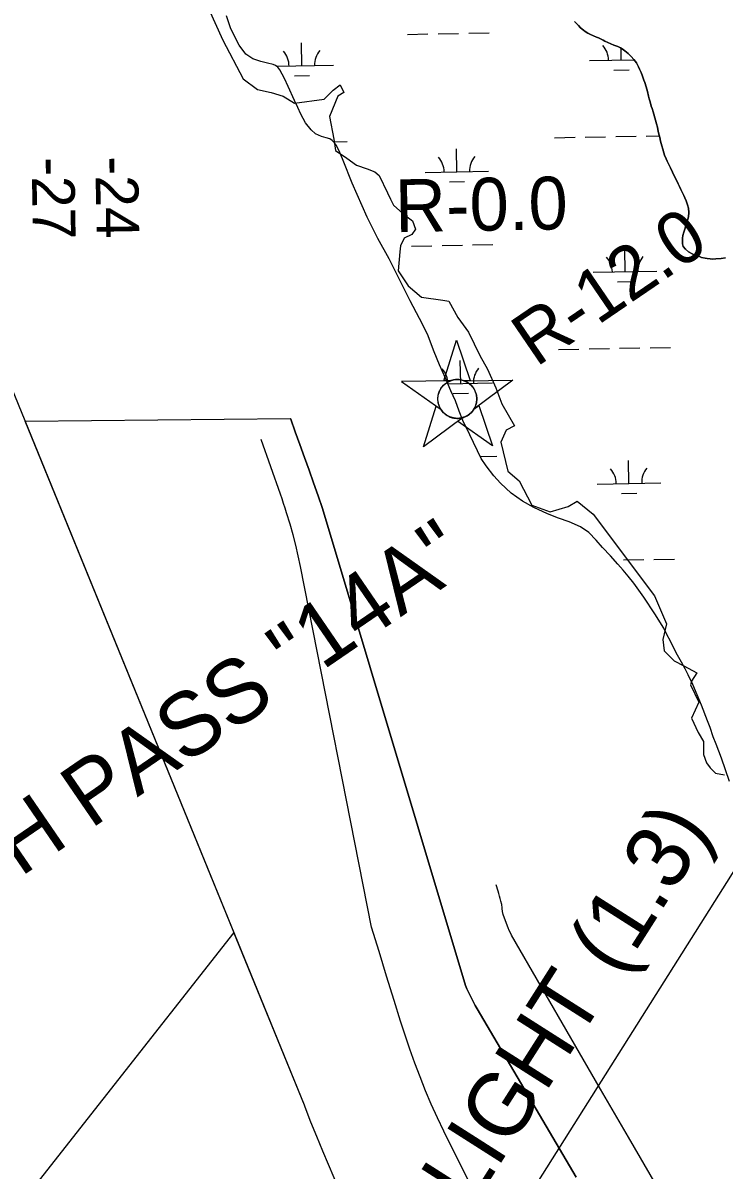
# Model space of a CAD drawing. Extents: x 3925854 to 3964121, y 224593 to 250589.
# Drawn here: x 3946690 to 3947792, y 237787 to 239589 of the extents above; entities that cross this region are included whole.
import ezdxf

# ---------------------------------------------------------------- set-up
doc = ezdxf.new("R2010")
doc.units = 0
for name, color, linetype in [('V-CHAN-NAID', 7, 'Continuous'), ('V-RIVR-EDGE', 7, 'Continuous'), ('V-RIVR-RANG', 7, 'Continuous'), ('V-RIVR-RANG-IDEN', 7, 'Continuous'), ('V-TOPO-DPTH', 7, 'Continuous'), ('V-TOPO-MINR', 7, 'Continuous'), ('V-TOPO-SHOR', 7, 'Continuous'), ('V-UTIL-LINE', 7, 'Continuous'), ('V-WETL-SWMP', 7, 'Continuous')]:
    doc.layers.add(name, color=color, linetype=linetype)

msp = doc.modelspace()

# ---------------------------------------------------------------- linework, layer by layer
at = {"layer": 'V-CHAN-NAID'}
for points in [[(3947361.111, 239026.765), (3947351.525, 239026.646), (3947371.41, 239090.529), (3947392.873, 239027.158), (3947383.286, 239027.04), (3947381.698, 239027.587), (3947379.592, 239028.166), (3947377.543, 239028.577), (3947375.502, 239028.845), (3947374.333, 239028.936), (3947372.797, 239028.988), (3947371.076, 239028.952), (3947369.707, 239028.855), (3947367.805, 239028.617), (3947366.444, 239028.372), (3947364.668, 239027.953), (3947363.146, 239027.503), (3947362.121, 239027.152)], [(3947361.111, 239026.765), (3947284.624, 239025.817), (3947347.062, 238981.625), (3947345.912, 238983.512), (3947345.07, 238985.124), (3947344.207, 238987.076), (3947343.471, 238989.116), (3947343.081, 238990.431), (3947342.688, 238992.05), (3947342.416, 238993.49), (3947342.197, 238995.084), (3947342.054, 238996.818), (3947342.011, 238998.398), (3947342.078, 239000.474), (3947342.229, 239002.095), (3947342.578, 239004.305), (3947343.022, 239006.237), (3947343.588, 239008.136), (3947344.21, 239009.827), (3947344.906, 239011.429), (3947345.69, 239012.98), (3947346.717, 239014.737), (3947347.719, 239016.227), (3947348.694, 239017.515), (3947349.674, 239018.68), (3947350.956, 239020.043), (3947351.988, 239021.028), (3947353.678, 239022.458), (3947354.873, 239023.351), (3947356.538, 239024.454), (3947358.251, 239025.433), (3947359.683, 239026.145)], [(3947383.286, 239027.04), (3947459.774, 239027.986), (3947398.45, 238982.261), (3947399.332, 238983.768), (3947400.274, 238985.634), (3947400.958, 238987.232), (3947401.659, 238989.201), (3947402.169, 238990.996), (3947402.535, 238992.643), (3947402.857, 238994.66), (3947403.012, 238996.236), (3947403.093, 238998.444), (3947403.023, 239000.505), (3947402.792, 239002.721), (3947402.491, 239004.473), (3947401.957, 239006.695), (3947401.275, 239008.822), (3947400.487, 239010.789), (3947399.811, 239012.22), (3947398.767, 239014.116), (3947397.671, 239015.817), (3947396.425, 239017.495), (3947395.134, 239019.009), (3947393.835, 239020.35), (3947392.174, 239021.85), (3947390.404, 239023.227), (3947388.698, 239024.371), (3947386.789, 239025.466), (3947385.303, 239026.199)], [(3947380.674, 238969.007), (3947319.35, 238923.282), (3947339.235, 238987.164), (3947347.062, 238981.625), (3947347.715, 238980.674), (3947349.134, 238978.842), (3947350.375, 238977.45), (3947351.87, 238975.976), (3947353.283, 238974.752), (3947354.759, 238973.625), (3947356.181, 238972.665), (3947357.879, 238971.662), (3947359.61, 238970.785), (3947361.417, 238970.009), (3947362.873, 238969.481), (3947364.511, 238968.984), (3947366.748, 238968.463), (3947368.285, 238968.206), (3947370.315, 238967.989), (3947371.854, 238967.915), (3947373.715, 238967.929), (3947375.402, 238968.04), (3947377.108, 238968.249), (3947379.004, 238968.597)], [(3947398.45, 238982.261), (3947406.136, 238987.993), (3947427.598, 238924.622), (3947372.987, 238963.276), (3947380.674, 238969.007), (3947382.33, 238969.515), (3947383.931, 238970.106), (3947386.071, 238971.062), (3947387.788, 238971.98), (3947389.632, 238973.13), (3947391.347, 238974.376), (3947392.875, 238975.651), (3947394.139, 238976.843), (3947395.495, 238978.29), (3947396.671, 238979.715), (3947397.762, 238981.209)]]:
    msp.add_lwpolyline(points, close=True, dxfattribs=at)
msp.add_circle((3947372.551, 238998.447), 30.541, dxfattribs=at)
at = {"layer": 'V-RIVR-EDGE'}
msp.add_lwpolyline([(3946981.586, 239611.735), (3947004.143, 239561.872), (3947036.198, 239501.325), (3947058.755, 239484.704), (3947080.125, 239479.955), (3947099.12, 239474.019), (3947116.928, 239463.334), (3947163.23, 239469.27), (3947177.476, 239483.516), (3947188.161, 239491.827), (3947194.097, 239479.955), (3947184.6, 239474.019), (3947171.54, 239441.964), (3947178.664, 239406.348), (3947181.038, 239388.539), (3947198.846, 239376.667), (3947214.28, 239365.982), (3947230.901, 239360.046), (3947242.773, 239355.298), (3947249.896, 239349.361), (3947262.956, 239322.056), (3947267.704, 239312.558), (3947272.453, 239303.06), (3947286.7, 239290.001), (3947302.134, 239278.129), (3947306.882, 239265.069), (3947300.946, 239256.759), (3947289.074, 239250.823), (3947283.138, 239238.951), (3947281.951, 239229.453), (3947279.577, 239199.773), (3947295.01, 239176.028), (3947316.38, 239158.22), (3947349.622, 239153.471), (3947359.12, 239152.284), (3947373.366, 239126.165), (3947389.987, 239103.608), (3947407.796, 239066.805), (3947419.668, 239045.435), (3947432.727, 239015.755), (3947442.225, 238990.823), (3947462.407, 238956.394), (3947449.348, 238949.271), (3947441.037, 238930.275), (3947451.722, 238885.161), (3947469.531, 238869.728), (3947489.713, 238831.737), (3947518.206, 238821.052), (3947546.699, 238829.362), (3947560.946, 238837.673), (3947585.877, 238817.49), (3947682.042, 238689.271), (3947701.037, 238645.344), (3947695.101, 238620.413), (3947697.475, 238602.605), (3947712.909, 238587.171), (3947728.343, 238578.861), (3947748.526, 238568.176), (3947740.215, 238555.116), (3947739.028, 238549.18), (3947752.087, 238521.874), (3947740.215, 238496.943), (3947750.9, 238474.386), (3947759.21, 238460.139), (3947759.21, 238448.267), (3947759.21, 238439.957), (3947763.959, 238426.897), (3947769.895, 238418.587), (3947778.206, 238410.276), (3947792.452, 238407.902)], dxfattribs=at)
at = {"layer": 'V-TOPO-DPTH'}
for points in [[(3946693.353, 238963.382), (3947110.256, 238967.95), (3947110.719, 238966.678), (3947117.981, 238946.654), (3947125.226, 238926.622), (3947132.458, 238906.587), (3947139.633, 238886.532), (3947146.747, 238866.454), (3947153.766, 238846.344), (3947160.724, 238826.212), (3947385.365, 238077.061), (3947387.577, 238071.644), (3947389.976, 238066.307), (3947392.498, 238061.022), (3947395.166, 238055.807), (3947397.905, 238050.63), (3947400.75, 238045.51), (3947403.666, 238040.429), (3947559.317, 237775.587)], [(3947132.294, 237888.663), (3946693.353, 238963.382)], [(3947021.379, 238160.231), (3946609.327, 237636.162)], [(3947132.294, 237888.663), (3947021.379, 238160.231)], [(3947188.051, 237753.814), (3947161.353, 237816.515), (3947151.809, 237839.392), (3947142.489, 237862.357), (3947133.505, 237885.456), (3947132.294, 237888.663)], [(3947188.051, 237753.814), (3947161.353, 237816.515), (3947151.809, 237839.392), (3947142.489, 237862.357), (3947133.505, 237885.456), (3947132.294, 237888.663)]]:
    msp.add_lwpolyline(points, dxfattribs=at)
at = {"layer": 'V-TOPO-MINR'}
for points in [[(3947132.294, 237888.663), (3946552.118, 239309.184), (3946236.204, 240123.225), (3945960.773, 240945.447)], [(3947559.317, 237775.587), (3947403.666, 238040.429), (3947400.75, 238045.51), (3947397.905, 238050.63), (3947395.166, 238055.807), (3947392.498, 238061.022), (3947389.976, 238066.307), (3947387.577, 238071.644), (3947385.365, 238077.061), (3947160.724, 238826.212), (3947153.766, 238846.344), (3947146.747, 238866.454), (3947139.633, 238886.532), (3947132.458, 238906.587), (3947125.226, 238926.622), (3947117.981, 238946.654), (3947110.719, 238966.678), (3947110.256, 238967.95)], [(3947390.846, 237768.494), (3947370.764, 237808.925), (3947351.227, 237848.155), (3947341.174, 237869.083), (3947331.526, 237890.189), (3947322.485, 237911.562), (3947313.848, 237933.113), (3947305.731, 237954.873), (3947297.903, 237976.732), (3947290.508, 237998.742), (3947283.401, 238020.853), (3947273.33, 238053.283), (3947261.434, 238091.693), (3947249.579, 238130.115), (3947237.785, 238168.556), (3947126.175, 238735.081), (3947122.67, 238751.847), (3947118.814, 238768.527), (3947114.43, 238785.075), (3947109.695, 238801.536), (3947104.241, 238819.422), (3947101.921, 238826.859), (3947099.537, 238834.275), (3947097.058, 238841.66), (3947094.515, 238849.024), (3947064.333, 238934.64)], [(3947684.829, 237763.478), (3947641.152, 237838.801), (3947597.516, 237914.148), (3947457.669, 238155.86), (3947456.281, 238158.356), (3947454.368, 238162.188), (3947453.243, 238164.81), (3947452.728, 238166.141), (3947444.518, 238188.391), (3947443.407, 238193.038), (3947443.105, 238197.833), (3947443.028, 238199.916), (3947442.624, 238202.862), (3947442.292, 238204.317), (3947440.926, 238209.4), (3947439.84, 238213.384), (3947438.737, 238217.364), (3947437.608, 238221.337), (3947436.461, 238225.305), (3947433.685, 238234.787)], [(3947188.051, 237753.814), (3947161.353, 237816.515), (3947151.809, 237839.392), (3947142.489, 237862.357), (3947133.505, 237885.456), (3947132.294, 237888.663)]]:
    msp.add_lwpolyline(points, dxfattribs=at)
at = {"layer": 'V-TOPO-SHOR'}
for points in [[(3947690.467, 239409.087), (3947689.498, 239413.032), (3947688.728, 239416.671), (3947687.571, 239421.826), (3947686.903, 239425.463), (3947685.445, 239430.825), (3947683.79, 239436.491), (3947682.721, 239440.336), (3947680.964, 239446.002), (3947679.889, 239449.441), (3947678.435, 239454.903), (3947677.259, 239458.446), (3947675.797, 239463.304), (3947674.724, 239466.745), (3947674.05, 239469.878), (3947672.987, 239474.326), (3947671.144, 239481.507), (3947669.002, 239488.691), (3947666.854, 239495.572), (3947665.481, 239499.521), (3947663.526, 239505.39), (3947661.068, 239511.467), (3947658.897, 239516.331), (3947657.121, 239519.98), (3947653.857, 239526.268), (3947649.779, 239531.756), (3947645.511, 239536.583), (3947641.118, 239540.925), (3947635.617, 239545.359), (3947631.593, 239548.327), (3947628.687, 239550.172), (3947624.452, 239552.232), (3947618.422, 239554.454), (3947604.146, 239560.774), (3947601.438, 239562.317), (3947597.625, 239564.172), (3947594.01, 239565.823), (3947590.895, 239566.863), (3947586.277, 239568.929), (3947581.659, 239570.994), (3947577.342, 239572.956), (3947573.235, 239575.721), (3947570.632, 239577.664), (3947566.237, 239581.746), (3947562.739, 239584.908), (3947559.147, 239588.779), (3947556.556, 239591.63)], [(3947794.01, 239220.001), (3947786.735, 239218.967), (3947778.66, 239218.347), (3947773.315, 239218.3), (3947769.786, 239218.64), (3947764.75, 239219.094), (3947761.727, 239219.631), (3947756.296, 239220.896), (3947752.878, 239222.041), (3947749.058, 239223.393), (3947746.144, 239224.331), (3947741.624, 239226.195), (3947735.505, 239229.486), (3947730.909, 239233.768), (3947727.523, 239237.94), (3947726.358, 239242.39), (3947726.106, 239247.234), (3947726.145, 239250.965), (3947726.792, 239255.094), (3947728.259, 239260.222), (3947729.721, 239265.049), (3947731.495, 239270.78), (3947733.571, 239276.508), (3947734.829, 239281.034), (3947735.474, 239284.759), (3947736.15, 239291.612), (3947735.412, 239298.376), (3947734.255, 239303.433), (3947731.9, 239309.81), (3947729.93, 239314.369), (3947728.353, 239317.816), (3947725.586, 239323.493), (3947723.612, 239327.648), (3947721.742, 239332.005), (3947719.569, 239336.568), (3947716.206, 239343.058), (3947712.852, 239350.052), (3947710.679, 239354.612), (3947707.42, 239361.303), (3947705.045, 239365.665), (3947702.184, 239371.949), (3947700.41, 239375.901), (3947698.149, 239381.673), (3947697.078, 239385.216), (3947695.321, 239390.88), (3947693.66, 239396.144), (3947692.691, 239399.988), (3947691.62, 239403.629), (3947690.467, 239409.087)]]:
    msp.add_lwpolyline(points, dxfattribs=at)
at = {"layer": 'V-UTIL-LINE'}
msp.add_line((3947949.336, 238483.295), (3945978.591, 235358.555), dxfattribs=at)
at = {"layer": 'V-WETL-SWMP'}
for p, q in [((3947294.366, 239571.233), (3947326.361, 239571.815)), ((3947342.358, 239572.106), (3947374.353, 239572.687)), ((3947390.35, 239572.978), (3947422.345, 239573.56)), ((3947128.174, 239521.773), (3947127.519, 239557.767)), ((3947629.999, 239530.898), (3947629.66, 239549.554)), ((3947580.007, 239529.989), (3947650.145, 239531.264)), ((3947088.695, 239521.056), (3947178.166, 239522.682)), ((3947618.281, 239515.251), (3947642.277, 239515.688)), ((3947116.456, 239506.127), (3947140.452, 239506.563)), ((3947177.837, 239402.586), (3947199.501, 239402.979)), ((3947525.355, 239408.905), (3947557.35, 239409.486)), ((3947573.347, 239409.777), (3947605.342, 239410.359)), ((3947621.34, 239410.65), (3947653.334, 239411.232)), ((3947669.332, 239411.522), (3947689.777, 239411.894)), ((3947371.711, 239355.36), (3947371.057, 239391.354)), ((3947321.72, 239354.451), (3947421.703, 239356.269)), ((3947359.994, 239339.714), (3947383.99, 239340.15)), ((3947300.414, 239238.613), (3947332.409, 239239.195)), ((3947348.406, 239239.486), (3947380.401, 239240.067)), ((3947396.398, 239240.358), (3947428.393, 239240.94)), ((3947636.047, 239198.278), (3947635.392, 239234.272)), ((3947586.055, 239197.369), (3947686.039, 239199.187)), ((3947624.329, 239182.631), (3947648.325, 239183.068)), ((3947531.403, 239076.284), (3947563.398, 239076.866)), ((3947579.396, 239077.157), (3947611.39, 239077.739)), ((3947627.388, 239078.03), (3947659.382, 239078.612)), ((3947675.38, 239078.902), (3947707.374, 239079.484)), ((3947377.76, 239022.74), (3947377.105, 239058.734)), ((3947357.425, 239022.371), (3947427.751, 239023.649)), ((3947366.042, 239007.094), (3947390.038, 239007.53)), ((3947408.579, 238907.85), (3947434.441, 238908.32)), ((3947642.095, 238865.658), (3947641.44, 238901.652)), ((3947592.103, 238864.749), (3947692.087, 238866.567)), ((3947630.377, 238850.011), (3947654.374, 238850.448)), ((3947633.436, 238745.41), (3947665.43, 238745.992)), ((3947681.428, 238746.282), (3947713.422, 238746.864))]:
    msp.add_line(p, q, dxfattribs=at)
for points in [[(3947548.419, 238805.415), (3947531.332, 238811.14), (3947513.952, 238817.877), (3947492.572, 238827.882), (3947474.621, 238837.953), (3947457.298, 238850.136), (3947440.317, 238866.148), (3947429.947, 238877.653), (3947417.702, 238893.212), (3947409.956, 238904.952), (3947392.208, 238942.295), (3947381.344, 238964.598), (3947375.548, 238979.485), (3947369.36, 238995.587), (3947362.159, 239011.194), (3947353.791, 239030.95), (3947344.728, 239051.822), (3947336.169, 239072.689), (3947325.463, 239100.437), (3947313.309, 239124.77), (3947298.266, 239152.563), (3947265.462, 239218.465), (3947247.54, 239250.726), (3947231.059, 239283.799), (3947207.107, 239337.607), (3947193.253, 239373.053), (3947186.655, 239388.453), (3947182.305, 239396.97), (3947179.419, 239400.732), (3947176.031, 239404.701), (3947172.224, 239407.161), (3947166.188, 239408.737), (3947158.947, 239410.729), (3947149.61, 239414.961), (3947142.613, 239421.085), (3947133.853, 239432.271), (3947126.73, 239445.659), (3947121.697, 239456.403), (3947116.565, 239467.249), (3947106.609, 239489.522), (3947100.99, 239502.088), (3947097.227, 239508.884), (3947093.665, 239515.478), (3947090.479, 239519.545), (3947086.98, 239522.507), (3947083.061, 239523.959), (3947074.104, 239525.868), (3947063.543, 239528.802), (3947051.481, 239532.76), (3947040.362, 239540.238), (3947029.514, 239554.27), (3947022.007, 239569.578), (3947016.181, 239581.642), (3947009.716, 239600.167)], [(3947556.556, 239591.629), (3947559.148, 239588.778), (3947562.739, 239584.908), (3947566.237, 239581.745), (3947570.633, 239577.665), (3947573.235, 239575.721), (3947577.342, 239572.955), (3947581.658, 239570.994), (3947586.277, 239568.929), (3947590.895, 239566.864), (3947594.011, 239565.823), (3947597.625, 239564.172), (3947601.439, 239562.316), (3947604.146, 239560.775), (3947618.423, 239554.454), (3947624.452, 239552.233), (3947628.687, 239550.172), (3947631.593, 239548.326), (3947635.617, 239545.36), (3947641.119, 239540.925), (3947645.512, 239536.583), (3947649.779, 239531.757), (3947653.857, 239526.268), (3947657.121, 239519.981), (3947658.898, 239516.331), (3947661.067, 239511.467), (3947663.525, 239505.39), (3947665.482, 239499.52), (3947666.853, 239495.572), (3947669.001, 239488.691), (3947671.145, 239481.507), (3947672.987, 239474.326), (3947674.05, 239469.877), (3947674.724, 239466.744), (3947675.798, 239463.303), (3947677.26, 239458.446), (3947678.434, 239454.904), (3947679.89, 239449.442), (3947680.964, 239446.002), (3947682.721, 239440.335), (3947683.791, 239436.491), (3947685.446, 239430.825), (3947686.904, 239425.464), (3947687.572, 239421.826), (3947688.729, 239416.67), (3947689.498, 239413.031), (3947690.466, 239409.087), (3947691.62, 239403.629), (3947692.691, 239399.987), (3947693.66, 239396.144), (3947695.32, 239390.881)], [(3947695.32, 239390.881), (3947697.077, 239385.215), (3947698.15, 239381.673), (3947700.41, 239375.901), (3947702.184, 239371.949), (3947705.044, 239365.665), (3947707.42, 239361.304), (3947710.679, 239354.613), (3947712.851, 239350.051), (3947716.207, 239343.057), (3947719.569, 239336.567), (3947721.741, 239332.005), (3947723.612, 239327.649), (3947725.587, 239323.493), (3947728.352, 239317.816), (3947729.93, 239314.37), (3947731.9, 239309.81), (3947734.255, 239303.432), (3947735.413, 239298.376), (3947736.149, 239291.611), (3947735.473, 239284.759), (3947734.829, 239281.034), (3947733.572, 239276.508), (3947731.495, 239270.78), (3947729.721, 239265.049), (3947728.259, 239260.223), (3947726.793, 239255.094), (3947726.145, 239250.965), (3947726.107, 239247.234), (3947726.359, 239242.39), (3947727.523, 239237.939), (3947730.909, 239233.769), (3947735.505, 239229.485), (3947741.623, 239226.194), (3947746.143, 239224.331), (3947749.058, 239223.393), (3947752.877, 239222.042), (3947756.295, 239220.897), (3947761.728, 239219.631), (3947764.749, 239219.095), (3947769.787, 239218.639), (3947773.314, 239218.3), (3947778.66, 239218.346), (3947786.736, 239218.968), (3947794.009, 239220.002)], [(3947800.278, 238397.126), (3947787.55, 238434.174), (3947779.101, 238455.847), (3947774.483, 238467.696), (3947769.492, 238482.474), (3947765.361, 238492.603), (3947755.833, 238517.212), (3947749.244, 238533.519), (3947742.552, 238549.626), (3947734.945, 238565.037), (3947730.201, 238574.365), (3947724.865, 238585.011), (3947718.521, 238595.769), (3947713.381, 238605.909), (3947707.353, 238617.974), (3947701.713, 238628.421), (3947696.972, 238638.154), (3947682.884, 238660.793), (3947665.505, 238686.996), (3947649.696, 238709.048), (3947640.732, 238720.034), (3947633.064, 238729.494), (3947624.687, 238738.76), (3947613.022, 238751.892), (3947600.753, 238765.132), (3947590.786, 238776.633), (3947579.107, 238788.353), (3947566.091, 238797.667), (3947548.419, 238805.415)]]:
    msp.add_lwpolyline(points, dxfattribs=at)
for centre, start, end in [((3947072.931, 239521.244), 0.269879, 41.813537), ((3947183.399, 239523.252), 140.269876, 181.813534), ((3947574.756, 239530.369), 0.269879, 41.813537), ((3947685.224, 239532.377), 181.468422, 181.813534), ((3947316.469, 239354.831), 0.269879, 41.813537), ((3947426.937, 239356.839), 140.269876, 181.813534), ((3947580.804, 239197.748), 0.269879, 41.813537), ((3947691.272, 239199.757), 140.269876, 181.813534), ((3947322.517, 239022.211), 0.269879, 41.813537), ((3947432.985, 239024.219), 140.269876, 181.813534), ((3947586.853, 238865.128), 0.269879, 41.813537), ((3947697.32, 238867.137), 140.269876, 181.813534)]:
    msp.add_arc(centre, 35.246, start, end, dxfattribs=at)

# ---------------------------------------------------------------- texts
at = {"layer": 'V-CHAN-NAID'}
for s, rotation, p in [('SOUTH PASS "14A"', 34.398576, (3946379.23, 238036.354)), ('NAVIGATION LIGHT (1.3)', 57.518436, (3946932.022, 236998.33))]:
    msp.add_text(s, height=100, rotation=rotation, dxfattribs=at).set_placement(p)
at = {"layer": 'V-RIVR-RANG'}
for s, p in [('-27', (3946703.65, 239377.949)), ('-24', (3946803.644, 239379.208))]:
    msp.add_text(s, height=67, rotation=271.030833, dxfattribs=at).set_placement(p)
at = {"layer": 'V-RIVR-RANG-IDEN'}
for s, rotation, p in [('R-0.0', 1.027133, (3947275.23, 239260.29)), ('R-12.0', 34.295994, (3947496.056, 239047.407))]:
    msp.add_text(s, height=83, rotation=rotation, dxfattribs=at).set_placement(p)

doc.saveas('drawing.dxf')
